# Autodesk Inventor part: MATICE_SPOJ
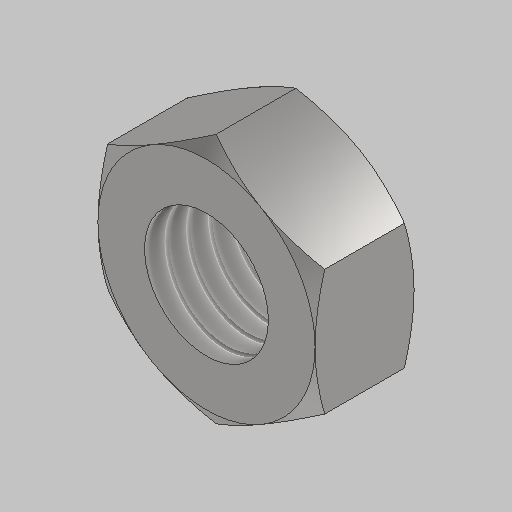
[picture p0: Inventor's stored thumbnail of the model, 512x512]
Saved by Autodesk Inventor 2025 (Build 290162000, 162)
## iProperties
Created: 2025-02
Part Number: MATICE_SPOJ
Material: Stainless Steel
Document SubType Name: Modeling
Designer: dansp
Density: 8 g/cm^3
Appearance: Semi-Polished
Mass: 0.763248 g
Surface Area: 1.74075 cm^2
Volume: 0.095406 cm^3
Author: dansp
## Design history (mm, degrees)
sketch "Sketch1"
  geometry: L1 (0, 5.67)-(0, -5.67) reference; L2 (-4.91, 0)-(4.91, 0) reference; L3 (0, 4.05)-(3.507, 2.025); L4 (3.507, 2.025)-(3.507, -2.025); L5 (3.507, -2.025)-(0, -4.05); L6 (0, -4.05)-(-3.507, -2.025); L7 (-3.507, -2.025)-(-3.507, 2.025); L8 (-3.507, 2.025)-(0, 4.05); C1 r 2 at (0, 0); 2 further points
  constraints: 12 end point, 2 coincident, 1 centre point, 1 point on line, 13 other
  dimensions: "d0" = 8.1 distance of L5.end L3.start; "d1" = 4 diameter of C1
extrude "Extrusion1" new body sketch "Sketch1" stored distance "d2" = 3.2; taper "d3" = 0 deg
thread "Thread1" dims "d4" = 12.8, "d5" = 0
sketch "Sketch4"
  geometry: L1 (3.507, -1.6)-(0, -1.6) reference; L2 (3.507, -1.6)-(3.507, 1.6) reference; L3 (0, 1.6)-(3.507, 1.6) reference; L4 (0, -1.6)-(0, 1.6) reference; L5 (3.507, 1.6)-(6.507, -0.132); L6 (3.507, 1.6)-(6.507, 1.6); L7 (6.507, 1.6)-(6.507, -0.132); 1 further point
  constraints: 6 end point, 1 horizontal, 1 perpendicular
  dimensions: "d6" = 30 deg angle of L6 L5; "d7" = 3 distance from line of L2.end L7
revolve "Revolution1" sketch "Sketch4" stored, may be unused: angle "d8" = 90 deg
mirror "Mirror1"
body "Solid1"
node "Projected Loop2"
